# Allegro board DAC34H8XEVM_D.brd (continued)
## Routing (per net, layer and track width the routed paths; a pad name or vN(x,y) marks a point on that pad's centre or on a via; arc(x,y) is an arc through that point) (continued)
DA1N: length 67.2
  TOP w0.127: U1.F1 40.01,68.76 39.66,68.76 39.42,68.53 39.42,68.51 39.36,68.45 39.36,68.43 39.35,68.42
  TOP w0.152: 39.35,68.42 28.46,57.53 26.95,57.53 26.82,57.4 26.82,56.61 26.52,56.31 26.1,56.31 25.8,56.61 25.8,58.62 25.67,58.75 25.48,58.75 25.35,58.62 25.35,56.61 25.05,56.31 24.63,56.31 24.33,56.61 24.33,58.62 24.2,58.75 24.01,58.75 23.87,58.62 23.87,56.61 23.58,56.31 23.15,56.31 22.86,56.61 22.86,58.62 22.72,58.75 22.53,58.75 22.4,58.62 22.4,56.61 22.1,56.31 21.68,56.31 21.38,56.61 21.38,58.62 21.25,58.75 21.06,58.75 20.93,58.62 20.93,56.61 20.63,56.31 20.21,56.31 19.91,56.61 19.91,58.62 19.78,58.75 19.59,58.75 19.45,58.62 19.45,56.61 19.16,56.31 18.73,56.31 18.44,56.61 18.44,58.62 18.3,58.75 18.11,58.75 17.98,58.62 17.98,56.61 17.68,56.31 17.26,56.31 16.96,56.61 16.96,57.4 16.83,57.53 16.36,57.53 15.29,56.46 10.93,56.46 9.18,54.7 9.18,54.33 9.17,54.32 v2(9.17,54.02)
  BOTTOM w0.152: J13.159 7.71,54.02 7.74,54.05 8.5,54.05 8.52,54.03 9.15,54.03 v2(9.17,54.02)
DA1P: length 67.7
  TOP w0.127: 39.15,68.62 39.15,68.62 39.55,69.02 39.96,69.02 39.98,69.03 40.3,69.03 40.7,68.64 U1.F2
  TOP w0.152: v2(8.72,54.52) 8.9,54.69 8.9,54.82 10.82,56.74 15.17,56.74 16.24,57.81 16.95,57.81 17.24,57.51 17.24,56.73 17.38,56.59 17.57,56.59 17.7,56.73 17.7,58.73 18,59.03 18.42,59.03 18.72,58.73 18.72,56.73 18.85,56.59 19.04,56.59 19.17,56.73 19.17,58.73 19.47,59.03 19.89,59.03 20.19,58.73 20.19,56.73 20.32,56.59 20.51,56.59 20.65,56.73 20.65,58.73 20.94,59.03 21.37,59.03 21.66,58.73 21.66,56.73 21.8,56.59 21.99,56.59 22.12,56.73 22.12,58.73 22.42,59.03 22.84,59.03 23.14,58.73 23.14,56.73 23.27,56.59 23.46,56.59 23.59,56.73 23.59,58.73 23.89,59.03 24.31,59.03 24.61,58.73 24.61,56.73 24.74,56.59 24.93,56.59 25.07,56.73 25.07,58.73 25.36,59.03 25.78,59.03 26.08,58.73 26.08,56.73 26.22,56.59 26.41,56.59 26.54,56.73 26.54,57.51 26.84,57.81 28.35,57.81 39.15,68.62
  BOTTOM w0.152: v2(8.72,54.52) 8.64,54.43 7.79,54.43 7.71,54.52 J13.157
DA2N: length 66.8
  L3_PWR w0.127: U1.F3 41.74,68.39 41.35,68 41.35,67.69 41.09,67.43 38.75,67.43 33.05,61.72 31.61,61.72 31.34,61.45 31.34,60.71 31.21,60.58 31.03,60.58 30.91,60.71 30.91,62.59 30.63,62.87 30.24,62.87 29.97,62.59 29.97,60.71 29.84,60.58 29.66,60.58 29.54,60.71 29.54,62.59 29.26,62.87 28.87,62.87 28.6,62.59 28.6,60.71 28.47,60.58 28.29,60.58 28.16,60.71 28.16,62.59 27.89,62.87 27.5,62.87 27.22,62.59 27.22,60.71 27.1,60.58 26.92,60.58 26.79,60.71 26.79,62.59 26.52,62.87 26.13,62.87 25.85,62.59 25.85,60.71 25.73,60.58 25.55,60.58 25.42,60.71 25.42,62.59 25.15,62.87 24.76,62.87 24.48,62.59 24.48,60.71 24.35,60.58 24.18,60.58 24.05,60.71 24.05,62.59 23.77,62.87 23.38,62.87 23.11,62.59 23.11,60.71 22.98,60.58 22.8,60.58 22.68,60.71 22.68,61.45 22.4,61.72 21.05,61.72 16.06,56.73 15.12,56.73 14.81,56.42 9.52,56.42 9.49,56.45 9,56.45 8.72,56.18 8.72,55.79 8.79,55.72 v2(8.79,55.45)
  BOTTOM w0.152: J13.153 7.71,55.52 7.73,55.53 8.7,55.53 v2(8.79,55.45)
DA2P: length 67.6
  L3_PWR w0.127: v2(9.19,55.98) 9.38,56.17 14.91,56.17 15.22,56.48 16.17,56.48 21.16,61.47 22.3,61.47 22.42,61.34 22.42,60.6 22.7,60.33 23.09,60.33 23.36,60.6 23.36,62.48 23.49,62.61 23.67,62.61 23.8,62.48 23.8,60.6 24.07,60.33 24.46,60.33 24.74,60.6 24.74,62.48 24.86,62.61 25.04,62.61 25.17,62.48 25.17,60.6 25.44,60.33 25.83,60.33 26.11,60.6 26.11,62.48 26.23,62.61 26.41,62.61 26.54,62.48 26.54,60.6 26.81,60.33 27.2,60.33 27.48,60.6 27.48,62.48 27.6,62.61 27.78,62.61 27.91,62.48 27.91,60.6 28.19,60.33 28.57,60.33 28.85,60.6 28.85,62.48 28.98,62.61 29.16,62.61 29.28,62.48 29.28,60.6 29.56,60.33 29.95,60.33 30.22,60.6 30.22,62.48 30.35,62.61 30.53,62.61 30.65,62.48 30.65,60.6 30.93,60.33 31.32,60.33 31.59,60.6 31.59,61.34 31.72,61.47 33.15,61.47 38.86,67.18 39.5,67.18 39.62,67.05 39.62,66.95 39.95,66.63 41.1,66.63 41.35,66.87 41.35,67.2 41.58,67.43 41.9,67.43 42.15,67.67 42.15,68 42.54,68.39 U1.F4
  BOTTOM w0.152: J13.151 7.71,56.02 7.77,55.96 9.17,55.96 v2(9.19,55.98)
DA3N: length 67.3
  TOP w0.127: U1.E1 40.01,69.57 39.45,69.57
  TOP w0.152: 39.45,69.57 39.09,69.57 31.99,62.47 31.99,62.46 30.11,60.58 29.07,60.58 28.77,60.88 28.77,61.44 28.64,61.57 28.45,61.57 28.32,61.44 28.32,59.89 28.02,59.59 27.6,59.59 27.3,59.89 27.3,61.44 27.17,61.57 26.98,61.57 26.84,61.44 26.84,59.89 26.55,59.59 26.12,59.59 25.83,59.89 25.83,61.44 25.69,61.57 25.5,61.57 25.37,61.44 25.37,59.89 25.07,59.59 24.65,59.59 24.35,59.89 24.35,61.44 24.22,61.57 24.03,61.57 23.9,61.44 23.9,59.89 23.6,59.59 23.18,59.59 22.88,59.89 22.88,61.44 22.75,61.57 22.56,61.57 22.42,61.44 22.42,59.89 22.13,59.59 21.71,59.59 21.41,59.89 21.41,61.44 21.27,61.57 21.08,61.57 20.95,61.44 20.95,59.89 20.65,59.59 20.23,59.59 19.93,59.89 19.93,61.44 19.8,61.57 19.61,61.57 19.48,61.44 19.48,59.89 19.18,59.59 18.76,59.59 18.46,59.89 18.46,61.44 18.33,61.57 18.14,61.57 18,61.44 18,59.89 17.71,59.59 17.29,59.59 16.99,59.89 16.99,60.38 15.95,61.42 15.95,62.04 15.68,62.31 15.3,62.31 11.44,58.45 10.24,58.45 9.75,57.96 9.56,57.96 9.21,57.61 9.21,57.06 v2(9.25,57.02)
  BOTTOM w0.152: v2(9.25,57.02) 9.23,57.04 7.73,57.04 7.71,57.02 J13.147
DA3P: length 67.8
  TOP w0.127: U1.E2 40.7,69.44 40.29,69.84 39.61,69.84
  TOP w0.152: v2(8.75,57.52) 8.75,57.54 9.45,58.24 9.64,58.24 10.12,58.72 11.33,58.72 15.19,62.59 15.8,62.59 16.23,62.15 16.23,61.53 17.27,60.5 17.27,60 17.4,59.87 17.59,59.87 17.72,60 17.72,61.55 18.02,61.85 18.44,61.85 18.74,61.55 18.74,60 18.87,59.87 19.06,59.87 19.2,60 19.2,61.55 19.5,61.85 19.92,61.85 20.21,61.55 20.21,60 20.35,59.87 20.54,59.87 20.67,60 20.67,61.55 20.97,61.85 21.39,61.85 21.69,61.55 21.69,60 21.82,59.87 22.01,59.87 22.14,60 22.14,61.55 22.44,61.85 22.86,61.85 23.16,61.55 23.16,60 23.29,59.87 23.48,59.87 23.62,60 23.62,61.55 23.92,61.85 24.34,61.85 24.63,61.55 24.63,60 24.77,59.87 24.96,59.87 25.09,60 25.09,61.55 25.39,61.85 25.81,61.85 26.11,61.55 26.11,60 26.24,59.87 26.43,59.87 26.56,60 26.56,61.55 26.86,61.85 27.28,61.85 27.58,61.55 27.58,60 27.71,59.87 27.9,59.87 28.04,60 28.04,61.55 28.33,61.85 28.76,61.85 29.05,61.55 29.05,60.99 29.19,60.86 30,60.86 31.71,62.57 31.71,62.59 38.97,69.85 39.6,69.85 39.61,69.84
  BOTTOM w0.152: v2(8.75,57.52) 8.69,57.45 7.77,57.45 7.71,57.52 J13.145
DA4N: length 66.9
  L3_PWR w0.127: v2(8.79,58.52) 8.98,58.71 8.98,58.89 9.25,59.17 9.64,59.17 9.92,58.89 10.34,58.89 12.75,61.31 12.75,61.41 12.75,61.41 12.75,62.56 12.74,62.58 12.74,62.76 15,65.02 15.03,65.02 15.9,65.89 18.98,65.89 19.25,65.61 19.25,65.05 19.38,64.92 19.56,64.92 19.68,65.05 19.68,66.58 19.96,66.85 20.35,66.85 20.62,66.58 20.62,65.05 20.75,64.92 20.93,64.92 21.05,65.05 21.05,66.58 21.33,66.85 21.72,66.85 21.99,66.58 21.99,65.05 22.12,64.92 22.3,64.92 22.43,65.05 22.43,66.58 22.7,66.85 23.09,66.85 23.37,66.58 23.37,65.05 23.49,64.92 23.67,64.92 23.8,65.05 23.8,66.58 24.07,66.85 24.46,66.85 24.74,66.58 24.74,65.05 24.86,64.92 25.04,64.92 25.17,65.05 25.17,66.58 25.44,66.85 25.83,66.85 26.11,66.58 26.11,65.05 26.24,64.92 26.41,64.92 26.54,65.05 26.54,66.58 26.82,66.85 27.21,66.85 27.48,66.58 27.48,65.05 27.61,64.92 27.79,64.92 27.91,65.05 27.91,66.58 28.19,66.85 28.58,66.85 28.85,66.58 28.85,65.05 28.98,64.92 29.16,64.92 29.28,65.05 29.28,66.58 29.56,66.85 29.95,66.85 30.22,66.58 30.22,66.01 30.35,65.89 32.71,65.89 35.07,68.25 39.56,68.25 39.75,68.44 39.75,68.8 39.98,69.03 40.42,69.03 40.43,69.04 41.23,69.04 41.62,69.44 U1.E3
  BOTTOM w0.152: v2(8.79,58.52) 8.79,58.52 7.71,58.52 J13.141
DA4P: length 67.4
  L3_PWR w0.127: v2(9.45,58.7) 9.51,58.64 10.44,58.64 13.01,61.2 13.01,61.52 13,61.52 13,62.56 13.02,62.58 13.02,62.65 16,65.63 18.87,65.63 19,65.51 19,64.94 19.27,64.67 19.66,64.67 19.94,64.94 19.94,66.47 20.06,66.6 20.24,66.6 20.37,66.47 20.37,64.94 20.64,64.67 21.03,64.67 21.31,64.94 21.31,66.47 21.44,66.6 21.61,66.6 21.74,66.47 21.74,64.94 22.02,64.67 22.41,64.67 22.68,64.94 22.68,66.47 22.81,66.6 22.99,66.6 23.11,66.47 23.11,64.94 23.39,64.67 23.78,64.67 24.05,64.94 24.05,66.47 24.18,66.6 24.36,66.6 24.48,66.47 24.48,64.94 24.76,64.67 25.15,64.67 25.42,64.94 25.42,66.47 25.55,66.6 25.73,66.6 25.86,66.47 25.86,64.94 26.13,64.67 26.52,64.67 26.8,64.94 26.8,66.47 26.92,66.6 27.1,66.6 27.23,66.47 27.23,64.94 27.5,64.67 27.89,64.67 28.17,64.94 28.17,66.47 28.29,66.6 28.47,66.6 28.6,66.47 28.6,64.94 28.87,64.67 29.26,64.67 29.54,64.94 29.54,66.47 29.66,66.6 29.84,66.6 29.97,66.47 29.97,65.91 30.25,65.63 32.82,65.63 35.18,68 39.66,68 39.91,68.25 39.92,68.25 39.92,68.24 41.1,68.24 41.33,68.47 41.33,68.79 41.58,69.03 41.89,69.03 42.3,69.44 U1.E4
  BOTTOM w0.152: v2(9.45,58.7) 9.29,58.7 8.99,59 8.6,59 8.59,59.02 7.71,59.02 J13.139
DA5N: length 66.9
  TOP w0.152: U1.D1 40.02,70.35 38.58,70.35 32.28,64.06 32.27,64.06 31.48,63.27 30.62,63.27 30.17,63.72 30.17,64.23 30.04,64.36 29.85,64.36 29.72,64.23 29.72,62.78 29.42,62.48 29,62.48 28.7,62.78 28.7,64.23 28.57,64.36 28.38,64.36 28.24,64.23 28.24,62.78 27.95,62.48 27.53,62.48 27.23,62.78 27.23,64.23 27.09,64.36 26.91,64.36 26.77,64.23 26.77,62.78 26.47,62.48 26.05,62.48 25.76,62.78 25.76,64.23 25.62,64.36 25.43,64.36 25.3,64.23 25.3,62.78 25,62.48 24.58,62.48 24.28,62.78 24.28,64.23 24.15,64.36 23.96,64.36 23.82,64.23 23.82,62.78 23.53,62.48 23.11,62.48 22.81,62.78 22.81,64.23 22.68,64.36 22.49,64.36 22.35,64.23 22.35,62.78 22.05,62.48 21.63,62.48 21.34,62.78 21.34,64.23 21.2,64.36 21.01,64.36 20.88,64.23 20.88,62.78 20.58,62.48 20.16,62.48 19.86,62.78 19.86,64.23 19.73,64.36 19.54,64.36 19.41,64.23 19.41,62.78 19.11,62.48 18.69,62.48 18.39,62.78 18.39,64.23 18.26,64.36 18.07,64.36 17.93,64.23 17.93,62.78 17.63,62.48 17.21,62.48 16.92,62.78 16.92,63.29 16.78,63.42 16.27,63.42 15.63,64.06 14.58,64.06 11.2,60.68 10.22,60.68 10.12,60.78 9.44,60.78 9.3,60.64 v2(9.3,60.02)
  BOTTOM w0.152: J13.135 7.71,60.02 7.73,60.04 9.28,60.04 v2(9.3,60.02)
DA5P: length 67.4
  TOP w0.127: 39.54,70.63 40.3,70.63 40.7,70.24 U1.D2
  TOP w0.152: 39.54,70.63 38.46,70.63 32.17,64.34 32.16,64.34 31.37,63.55 30.74,63.55 30.45,63.84 30.45,64.35 30.16,64.64 29.74,64.64 29.44,64.35 29.44,62.9 29.3,62.76 29.12,62.76 28.98,62.9 28.98,64.35 28.68,64.64 28.26,64.64 27.97,64.35 27.97,62.9 27.83,62.76 27.64,62.76 27.51,62.9 27.51,64.35 27.21,64.64 26.79,64.64 26.49,64.35 26.49,62.9 26.36,62.76 26.17,62.76 26.03,62.9 26.03,64.35 25.74,64.64 25.32,64.64 25.02,64.35 25.02,62.9 24.88,62.76 24.7,62.76 24.56,62.9 24.56,64.35 24.26,64.64 23.84,64.64 23.55,64.35 23.55,62.9 23.41,62.76 23.22,62.76 23.09,62.9 23.09,64.35 22.79,64.64 22.37,64.64 22.07,64.35 22.07,62.9 21.94,62.76 21.75,62.76 21.62,62.9 21.62,64.35 21.32,64.64 20.9,64.64 20.6,64.35 20.6,62.9 20.47,62.76 20.28,62.76 20.14,62.9 20.14,64.35 19.84,64.64 19.42,64.64 19.13,64.35 19.13,62.9 18.99,62.76 18.8,62.76 18.67,62.9 18.67,64.35 18.37,64.64 17.95,64.64 17.65,64.35 17.65,62.9 17.52,62.76 17.33,62.76 17.2,62.9 17.2,63.41 16.9,63.7 16.38,63.7 15.75,64.34 14.46,64.34 11.09,60.96 10.34,60.96 10.24,61.06 9.32,61.06 8.81,60.55 v2(8.81,60.52)
  BOTTOM w0.152: v2(8.81,60.52) 8.74,60.45 7.78,60.45 7.71,60.52 J13.133
DA6N: length 67.5
  L3_PWR w0.127: U1.D3 41.66,70.24 41.52,70.38 41.4,70.38 41.33,70.31 41.33,70.07 41.1,69.84 39.98,69.84 39.75,70.07 39.75,70.44 39.67,70.51 35.64,70.51 34.4,69.27 30.77,69.27 30.36,68.86 30.36,68.3 30.09,68.02 29.7,68.02 29.42,68.3 29.42,69.83 29.3,69.95 29.12,69.95 28.99,69.83 28.99,68.3 28.72,68.02 28.33,68.02 28.05,68.3 28.05,69.83 27.93,69.95 27.75,69.95 27.62,69.83 27.62,68.3 27.35,68.02 26.96,68.02 26.68,68.3 26.68,69.83 26.55,69.95 26.38,69.95 26.25,69.83 26.25,68.3 25.97,68.02 25.58,68.02 25.31,68.3 25.31,69.83 25.18,69.95 25,69.95 24.88,69.83 24.88,68.3 24.6,68.02 24.21,68.02 23.94,68.3 23.94,69.83 23.81,69.95 23.63,69.95 23.51,69.83 23.51,68.3 23.23,68.02 22.84,68.02 22.57,68.3 22.57,69.83 22.44,69.95 22.26,69.95 22.13,69.83 22.13,68.3 21.86,68.02 21.47,68.02 21.19,68.3 21.19,69.83 21.07,69.95 20.89,69.95 20.76,69.83 20.76,68.3 20.49,68.02 20.1,68.02 19.82,68.3 19.82,69.83 19.7,69.95 19.52,69.95 19.39,69.83 19.39,68.3 19.12,68.02 18.73,68.02 18.45,68.3 18.45,68.86 18.32,68.99 16.43,68.99 9.22,61.77 v2(9.22,61.52)
  BOTTOM w0.152: J13.129 7.71,61.52 7.78,61.59 8.48,61.59 8.53,61.54 9.2,61.54 v2(9.22,61.52)
DA6P: length 67.3
  L3_PWR w0.127: v2(8.73,62.02) 9.11,62.02 16.33,69.24 18.43,69.24 18.71,68.97 18.71,68.4 18.83,68.28 19.01,68.28 19.14,68.4 19.14,69.93 19.41,70.21 19.8,70.21 20.08,69.93 20.08,68.4 20.2,68.28 20.38,68.28 20.51,68.4 20.51,69.93 20.78,70.21 21.17,70.21 21.45,69.93 21.45,68.4 21.58,68.28 21.75,68.28 21.88,68.4 21.88,69.93 22.16,70.21 22.55,70.21 22.82,69.93 22.82,68.4 22.95,68.28 23.13,68.28 23.25,68.4 23.25,69.93 23.53,70.21 23.92,70.21 24.19,69.93 24.19,68.4 24.32,68.28 24.5,68.28 24.62,68.4 24.62,69.93 24.9,70.21 25.29,70.21 25.56,69.93 25.56,68.4 25.69,68.28 25.87,68.28 26,68.4 26,69.93 26.27,70.21 26.66,70.21 26.93,69.93 26.93,68.4 27.06,68.28 27.24,68.28 27.37,68.4 27.37,69.93 27.64,70.21 28.03,70.21 28.31,69.93 28.31,68.4 28.43,68.28 28.61,68.28 28.74,68.4 28.74,69.93 29.01,70.21 29.4,70.21 29.68,69.93 29.68,68.4 29.8,68.28 29.98,68.28 30.11,68.4 30.11,68.97 30.66,69.52 34.29,69.52 35.53,70.76 39.78,70.76 39.91,70.63 41.9,70.63 42.3,70.24 U1.D4
  BOTTOM w0.152: J13.127 7.71,62.02 7.78,61.95 8.66,61.95 v2(8.73,62.02)
DA7N: length 67
  TOP w0.127: U1.C1 40.01,71.16 38.73,71.16
  TOP w0.152: v2(9.22,63.02) 9.22,63.6 9.43,63.81 12.85,63.81 15.36,66.32 18.47,66.32 18.6,66.19 18.6,65.52 18.9,65.23 19.32,65.23 19.62,65.52 19.62,67.28 19.75,67.41 19.94,67.41 20.07,67.28 20.07,65.52 20.37,65.23 20.79,65.23 21.09,65.52 21.09,67.28 21.22,67.41 21.41,67.41 21.55,67.28 21.55,65.52 21.84,65.23 22.26,65.23 22.56,65.52 22.56,67.28 22.7,67.41 22.89,67.41 23.02,67.28 23.02,65.52 23.32,65.23 23.74,65.23 24.04,65.52 24.04,67.28 24.17,67.41 24.36,67.41 24.49,67.28 24.49,65.52 24.79,65.23 25.21,65.23 25.51,65.52 25.51,67.28 25.64,67.41 25.83,67.41 25.97,67.28 25.97,65.52 26.26,65.23 26.68,65.23 26.98,65.52 26.98,67.28 27.12,67.41 27.31,67.41 27.44,67.28 27.44,65.52 27.74,65.23 28.16,65.23 28.45,65.52 28.45,67.28 28.59,67.41 28.78,67.41 28.91,67.28 28.91,65.52 29.21,65.23 29.63,65.23 29.93,65.52 29.93,67.28 30.06,67.41 30.25,67.41 30.39,67.28 30.39,66.62 30.68,66.32 33.42,66.32 38.27,71.17 38.6,71.17 38.61,71.16 38.73,71.16
  BOTTOM w0.152: J13.123 7.71,63.02 7.81,63.12 8.48,63.12 8.56,63.04 9.2,63.04 v2(9.22,63.02)
DA7P: length 67.5
  TOP w0.127: 38.73,71.45 38.74,71.44 39.96,71.44 39.97,71.44 40.31,71.44 40.31,71.44 40.37,71.44 40.77,71.04 U1.C2
  TOP w0.152: v2(8.76,63.52) 8.76,63.54 9.31,64.09 12.73,64.09 15.24,66.6 18.58,66.6 18.88,66.3 18.88,65.64 19.01,65.51 19.2,65.51 19.34,65.64 19.34,67.39 19.63,67.69 20.05,67.69 20.35,67.39 20.35,65.64 20.49,65.51 20.68,65.51 20.81,65.64 20.81,67.39 21.11,67.69 21.53,67.69 21.83,67.39 21.83,65.64 21.96,65.51 22.15,65.51 22.28,65.64 22.28,67.39 22.58,67.69 23,67.69 23.3,67.39 23.3,65.64 23.43,65.51 23.62,65.51 23.76,65.64 23.76,67.39 24.05,67.69 24.47,67.69 24.77,67.39 24.77,65.64 24.91,65.51 25.1,65.51 25.23,65.64 25.23,67.39 25.53,67.69 25.95,67.69 26.25,67.39 26.25,65.64 26.38,65.51 26.57,65.51 26.7,65.64 26.7,67.39 27,67.69 27.42,67.69 27.72,67.39 27.72,65.64 27.85,65.51 28.04,65.51 28.18,65.64 28.18,67.39 28.47,67.69 28.89,67.69 29.19,67.39 29.19,65.64 29.33,65.51 29.51,65.51 29.65,65.64 29.65,67.39 29.95,67.69 30.37,67.69 30.66,67.39 30.66,66.73 30.8,66.6 33.3,66.6 38.15,71.45 38.73,71.45
  BOTTOM w0.152: J13.121 7.71,63.52 7.81,63.42 8.66,63.42 v2(8.76,63.52)
DA8N: length 66.8
  L3_PWR w0.127: U1.C3 41.62,71.04 41.23,71.43 39.91,71.43 39.67,71.68 39.67,71.85 39.54,71.98 38.23,71.98 38.11,71.85 38.11,71.58 37.83,71.31 37.44,71.31 37.17,71.58 37.17,72.52 37.04,72.64 36.86,72.64 36.73,72.52 36.73,71.58 36.46,71.31 36.07,71.31 35.79,71.58 35.79,72.52 35.67,72.64 35.49,72.64 35.36,72.52 35.36,71.58 35.09,71.31 34.7,71.31 34.42,71.58 34.42,72.52 34.3,72.64 34.12,72.64 33.99,72.52 33.99,71.58 33.72,71.31 33.33,71.31 33.05,71.58 33.05,72.52 32.93,72.64 32.75,72.64 32.62,72.52 32.62,71.58 32.34,71.31 31.96,71.31 31.68,71.58 31.68,72.52 31.55,72.64 31.37,72.64 31.25,72.52 31.25,71.58 30.97,71.31 30.58,71.31 30.31,71.58 30.31,72.52 30.18,72.64 30,72.64 29.88,72.52 29.88,71.58 29.6,71.31 29.21,71.31 28.94,71.58 28.94,72.52 28.81,72.64 28.63,72.64 28.51,72.52 28.51,71.58 28.23,71.31 27.84,71.31 27.57,71.58 27.57,72.52 27.44,72.64 27.26,72.64 27.13,72.52 27.13,71.58 26.86,71.31 26.47,71.31 26.19,71.58 26.19,72.52 26.07,72.64 25.89,72.64 25.76,72.52 25.76,71.58 25.49,71.31 25.1,71.31 24.82,71.58 24.82,72.52 24.7,72.64 24.52,72.64 24.39,72.52 24.39,71.58 24.12,71.31 23.73,71.31 23.45,71.58 23.45,72.52 23.32,72.64 23.15,72.64 23.02,72.52 23.02,71.58 22.74,71.31 22.35,71.31 22.08,71.58 22.08,72.52 21.95,72.64 21.77,72.64 21.65,72.52 21.65,71.58 21.37,71.31 20.98,71.31 20.71,71.58 20.71,72.52 20.58,72.64 20.4,72.64 20.28,72.52 20.28,71.58 20,71.31 19.61,71.31 19.34,71.58 19.34,72.52 19.21,72.64 19.03,72.64 18.9,72.52 18.9,72.25 18.63,71.98 17.52,71.98 15.21,69.67 12.9,69.67 11.92,70.65 11.92,70.65 11.52,71.06 10.47,71.06 10.3,71.22 9.76,71.22 9.54,71.01 8.85,71.01 v2(8.84,71.02)
  BOTTOM w0.152: v2(8.84,71.02) 8.74,71.12 7.79,71.12 7.71,71.04 J13.111
DA8P: length 67.7
  L3_PWR w0.127: v2(9.35,71.48) 10.41,71.48 10.57,71.31 11.62,71.31 12.18,70.76 12.18,70.76 13,69.93 15.11,69.93 17.41,72.23 18.52,72.23 18.65,72.36 18.65,72.62 18.93,72.9 19.31,72.9 19.59,72.62 19.59,71.69 19.72,71.56 19.9,71.56 20.02,71.69 20.02,72.62 20.3,72.9 20.69,72.9 20.96,72.62 20.96,71.69 21.09,71.56 21.27,71.56 21.39,71.69 21.39,72.62 21.67,72.9 22.06,72.9 22.33,72.62 22.33,71.69 22.46,71.56 22.64,71.56 22.76,71.69 22.76,72.62 23.04,72.9 23.43,72.9 23.7,72.62 23.7,71.69 23.83,71.56 24.01,71.56 24.14,71.69 24.14,72.62 24.41,72.9 24.8,72.9 25.08,72.62 25.08,71.69 25.2,71.56 25.38,71.56 25.51,71.69 25.51,72.62 25.78,72.9 26.17,72.9 26.45,72.62 26.45,71.69 26.57,71.56 26.75,71.56 26.88,71.69 26.88,72.62 27.15,72.9 27.54,72.9 27.82,72.62 27.82,71.69 27.95,71.56 28.12,71.56 28.25,71.69 28.25,72.62 28.53,72.9 28.92,72.9 29.19,72.62 29.19,71.69 29.32,71.56 29.5,71.56 29.62,71.69 29.62,72.62 29.9,72.9 30.29,72.9 30.56,72.62 30.56,71.69 30.69,71.56 30.87,71.56 30.99,71.69 30.99,72.62 31.27,72.9 31.66,72.9 31.93,72.62 31.93,71.69 32.06,71.56 32.24,71.56 32.37,71.69 32.37,72.62 32.64,72.9 33.03,72.9 33.31,72.62 33.31,71.69 33.43,71.56 33.61,71.56 33.74,71.69 33.74,72.62 34.01,72.9 34.4,72.9 34.68,72.62 34.68,71.69 34.8,71.56 34.98,71.56 35.11,71.69 35.11,72.62 35.38,72.9 35.77,72.9 36.05,72.62 36.05,71.69 36.18,71.56 36.35,71.56 36.48,71.69 36.48,72.62 36.76,72.9 37.15,72.9 37.42,72.62 37.42,71.69 37.55,71.56 37.73,71.56 37.85,71.69 37.85,71.96 38.13,72.23 41.1,72.23 41.33,72 41.33,71.69 41.58,71.44 41.89,71.44 42.3,71.04 U1.C4
  BOTTOM w0.152: v2(9.35,71.48) 9.06,71.48 9.04,71.5 7.74,71.5 7.71,71.54 J13.109
DA9N: length 67.5
  TOP w0.127: 39.44,72.1 39.56,72.1 39.57,72.11 39.87,72.11 U1.B1
  TOP w0.152: 39.44,72.1 37.82,72.1 37.5,71.78 36.39,71.78 36.09,72.08 36.09,72.43 35.96,72.57 35.77,72.57 35.63,72.43 35.63,71.29 35.33,70.99 34.91,70.99 34.62,71.29 34.62,72.43 34.48,72.57 34.29,72.57 34.16,72.43 34.16,71.29 33.86,70.99 33.44,70.99 33.14,71.29 33.14,72.43 33.01,72.57 32.82,72.57 32.69,72.43 32.69,71.29 32.39,70.99 31.97,70.99 31.67,71.29 31.67,72.43 31.54,72.57 31.35,72.57 31.21,72.43 31.21,71.29 30.91,70.99 30.49,70.99 30.2,71.29 30.2,72.43 30.06,72.57 29.87,72.57 29.74,72.43 29.74,71.29 29.44,70.99 29.02,70.99 28.72,71.29 28.72,72.43 28.59,72.57 28.4,72.57 28.27,72.43 28.27,71.29 27.97,70.99 27.55,70.99 27.25,71.29 27.25,72.43 27.12,72.57 26.93,72.57 26.79,72.43 26.79,71.29 26.5,70.99 26.07,70.99 25.78,71.29 25.78,72.43 25.64,72.57 25.45,72.57 25.32,72.43 25.32,71.29 25.02,70.99 24.6,70.99 24.3,71.29 24.3,72.43 24.17,72.57 23.98,72.57 23.85,72.43 23.85,71.29 23.55,70.99 23.13,70.99 22.83,71.29 22.83,72.43 22.7,72.57 22.51,72.57 22.37,72.43 22.37,71.29 22.08,70.99 21.65,70.99 21.36,71.29 21.36,72.43 21.22,72.57 21.03,72.57 20.9,72.43 20.9,71.29 20.6,70.99 20.18,70.99 19.88,71.29 19.88,72.43 19.75,72.57 19.56,72.57 19.43,72.43 19.43,71.29 19.13,70.99 18.71,70.99 18.41,71.29 18.41,72.43 18.28,72.57 18.09,72.57 17.95,72.43 17.95,72.09 16.02,70.15 15.09,70.15 12.52,72.72 9.45,72.72 v2(9.27,72.54)
  BOTTOM w0.152: v2(9.27,72.54) 9.25,72.56 8.63,72.56 8.56,72.62 7.79,72.62 ; 7.71,72.54 7.79,72.62 ; 7.79,72.62 7.79,72.53 J13.105
DA9P: length 67.4
  TOP w0.127: 39.44,72.38 39.88,72.38 U1.A1
  TOP w0.152: 39.44,72.38 37.71,72.38 37.39,72.06 36.5,72.06 36.37,72.19 36.37,72.55 36.07,72.85 35.65,72.85 35.35,72.55 35.35,71.41 35.22,71.27 35.03,71.27 34.9,71.41 34.9,72.55 34.6,72.85 34.18,72.85 33.88,72.55 33.88,71.41 33.75,71.27 33.56,71.27 33.42,71.41 33.42,72.55 33.12,72.85 32.7,72.85 32.41,72.55 32.41,71.41 32.27,71.27 32.08,71.27 31.95,71.41 31.95,72.55 31.65,72.85 31.23,72.85 30.93,72.55 30.93,71.41 30.8,71.27 30.61,71.27 30.48,71.41 30.48,72.55 30.18,72.85 29.76,72.85 29.46,72.55 29.46,71.41 29.33,71.27 29.14,71.27 29,71.41 29,72.55 28.71,72.85 28.28,72.85 27.99,72.55 27.99,71.41 27.85,71.27 27.66,71.27 27.53,71.41 27.53,72.55 27.23,72.85 26.81,72.85 26.51,72.55 26.51,71.41 26.38,71.27 26.19,71.27 26.06,71.41 26.06,72.55 25.76,72.85 25.34,72.85 25.04,72.55 25.04,71.41 24.91,71.27 24.72,71.27 24.58,71.41 24.58,72.55 24.29,72.85 23.86,72.85 23.57,72.55 23.57,71.41 23.43,71.27 23.24,71.27 23.11,71.41 23.11,72.55 22.81,72.85 22.39,72.85 22.09,72.55 22.09,71.41 21.96,71.27 21.77,71.27 21.64,71.41 21.64,72.55 21.34,72.85 20.92,72.85 20.62,72.55 20.62,71.41 20.49,71.27 20.3,71.27 20.16,71.41 20.16,72.55 19.87,72.85 19.44,72.85 19.15,72.55 19.15,71.41 19.01,71.27 18.82,71.27 18.69,71.41 18.69,72.55 18.39,72.85 17.97,72.85 17.67,72.55 17.67,72.21 15.9,70.43 15.2,70.43 12.64,73 11.04,73 11,73.04 v2(8.83,73.04)
  BOTTOM w0.152: 7.71,73.04 7.77,72.97 ; 7.77,72.97 7.77,73.04 J13.103 ; 7.77,72.97 8.76,72.97 v2(8.83,73.04)
DA10N: length 67.8
  TOP w0.127: U1.B2 40.91,71.84 40.53,72.22 40.53,73.03
  TOP w0.152: v2(9.25,74.04) 13.26,74.04 14,73.3 15.29,73.3 16.03,74.04 16.51,74.04 16.81,74.34 16.81,74.62 16.94,74.75 17.13,74.75 17.26,74.62 17.26,73.63 17.56,73.33 17.98,73.33 18.28,73.63 18.28,74.62 18.41,74.75 18.6,74.75 18.74,74.62 18.74,73.63 19.03,73.33 19.45,73.33 19.75,73.63 19.75,74.62 19.89,74.75 20.08,74.75 20.21,74.62 20.21,73.63 20.51,73.33 20.93,73.33 21.23,73.63 21.23,74.62 21.36,74.75 21.55,74.75 21.68,74.62 21.68,73.63 21.98,73.33 22.4,73.33 22.7,73.63 22.7,74.62 22.83,74.75 23.02,74.75 23.16,74.62 23.16,73.63 23.45,73.33 23.87,73.33 24.17,73.63 24.17,74.62 24.31,74.75 24.5,74.75 24.63,74.62 24.63,73.63 24.93,73.33 25.35,73.33 25.65,73.63 25.65,74.62 25.78,74.75 25.97,74.75 26.1,74.62 26.1,73.63 26.4,73.33 26.82,73.33 27.12,73.63 27.12,74.62 27.25,74.75 27.44,74.75 27.58,74.62 27.58,73.63 27.87,73.33 28.29,73.33 28.59,73.63 28.59,74.62 28.73,74.75 28.91,74.75 29.05,74.62 29.05,73.63 29.35,73.33 29.77,73.33 30.06,73.63 30.06,74.62 30.2,74.75 30.39,74.75 30.52,74.62 30.52,73.63 30.82,73.33 31.24,73.33 31.54,73.63 31.54,74.62 31.67,74.75 31.86,74.75 32,74.62 32,73.63 32.29,73.33 32.71,73.33 33.01,73.63 33.01,74.62 33.14,74.75 33.33,74.75 33.47,74.62 33.47,73.63 33.77,73.33 34.19,73.33 34.48,73.63 34.48,74.62 34.62,74.75 34.81,74.75 34.94,74.62 34.94,73.63 35.24,73.33 35.66,73.33 35.96,73.63 35.96,74.62 36.09,74.75 36.28,74.75 36.41,74.62 36.41,73.63 36.71,73.33 37.13,73.33 37.43,73.63 37.43,73.91 37.56,74.04 38.61,74.04 39.35,73.3 40.26,73.3 40.53,73.03
  BOTTOM w0.152: J13.99 7.71,74.04 7.79,74.12 8.54,74.12 8.6,74.06 9.23,74.06 v2(9.25,74.04)
DA10P: length 67.4
  TOP w0.127: 40.82,73.14 40.82,72.76 U1.A2
  TOP w0.152: 40.82,73.14 40.38,73.58 39.46,73.58 38.72,74.32 37.45,74.32 37.15,74.02 37.15,73.74 37.02,73.61 36.83,73.61 36.69,73.74 36.69,74.73 36.4,75.03 35.98,75.03 35.68,74.73 35.68,73.74 35.54,73.61 35.35,73.61 35.22,73.74 35.22,74.73 34.92,75.03 34.5,75.03 34.2,74.73 34.2,73.74 34.07,73.61 33.88,73.61 33.75,73.74 33.75,74.73 33.45,75.03 33.03,75.03 32.73,74.73 32.73,73.74 32.6,73.61 32.41,73.61 32.27,73.74 32.27,74.73 31.98,75.03 31.56,75.03 31.26,74.73 31.26,73.74 31.12,73.61 30.94,73.61 30.8,73.74 30.8,74.73 30.5,75.03 30.08,75.03 29.79,74.73 29.79,73.74 29.65,73.61 29.46,73.61 29.33,73.74 29.33,74.73 29.03,75.03 28.61,75.03 28.31,74.73 28.31,73.74 28.18,73.61 27.99,73.61 27.85,73.74 27.85,74.73 27.56,75.03 27.14,75.03 26.84,74.73 26.84,73.74 26.71,73.61 26.52,73.61 26.38,73.74 26.38,74.73 26.08,75.03 25.66,75.03 25.37,74.73 25.37,73.74 25.23,73.61 25.04,73.61 24.91,73.74 24.91,74.73 24.61,75.03 24.19,75.03 23.89,74.73 23.89,73.74 23.76,73.61 23.57,73.61 23.44,73.74 23.44,74.73 23.14,75.03 22.72,75.03 22.42,74.73 22.42,73.74 22.29,73.61 22.1,73.61 21.96,73.74 21.96,74.73 21.66,75.03 21.24,75.03 20.95,74.73 20.95,73.74 20.81,73.61 20.62,73.61 20.49,73.74 20.49,74.73 20.19,75.03 19.77,75.03 19.47,74.73 19.47,73.74 19.34,73.61 19.15,73.61 19.02,73.74 19.02,74.73 18.72,75.03 18.3,75.03 18,74.73 18,73.74 17.87,73.61 17.68,73.61 17.54,73.74 17.54,74.73 17.25,75.03 16.82,75.03 16.53,74.73 16.53,74.45 16.39,74.32 15.91,74.32 15.17,73.58 14.11,73.58 13.37,74.32 9.61,74.32 9.44,74.5 8.84,74.5 v2(8.8,74.54)
  BOTTOM w0.152: J13.97 7.71,74.54 7.77,74.47 8.73,74.47 v2(8.8,74.54)
DA11N: length 67.4
  TOP w0.127: 41.33,73.28 41.34,73.28 41.34,73.27 41.33,73.26 41.33,72.23 41.73,71.84 U1.B3
  TOP w0.152: v2(9.25,75.54) 9.63,75.92 13.23,75.92 14.1,75.06 15.44,75.06 16.74,76.35 17.48,76.35 17.61,76.22 17.61,75.94 17.91,75.64 18.33,75.64 18.63,75.94 18.63,76.93 18.76,77.06 18.95,77.06 19.09,76.93 19.09,75.94 19.38,75.64 19.8,75.64 20.1,75.94 20.1,76.93 20.24,77.06 20.42,77.06 20.56,76.93 20.56,75.94 20.86,75.64 21.28,75.64 21.57,75.94 21.57,76.93 21.71,77.06 21.9,77.06 22.03,76.93 22.03,75.94 22.33,75.64 22.75,75.64 23.05,75.94 23.05,76.93 23.18,77.06 23.37,77.06 23.5,76.93 23.5,75.94 23.8,75.64 24.22,75.64 24.52,75.94 24.52,76.93 24.65,77.06 24.84,77.06 24.98,76.93 24.98,75.94 25.28,75.64 25.7,75.64 25.99,75.94 25.99,76.93 26.13,77.06 26.32,77.06 26.45,76.93 26.45,75.94 26.75,75.64 27.17,75.64 27.47,75.94 27.47,76.93 27.6,77.06 27.79,77.06 27.92,76.93 27.92,75.94 28.22,75.64 28.64,75.64 28.94,75.94 28.94,76.93 29.07,77.06 29.26,77.06 29.4,76.93 29.4,75.94 29.7,75.64 30.12,75.64 30.41,75.94 30.41,76.93 30.55,77.06 30.74,77.06 30.87,76.93 30.87,75.94 31.17,75.64 31.59,75.64 31.89,75.94 31.89,76.93 32.02,77.06 32.21,77.06 32.34,76.93 32.34,75.94 32.64,75.64 33.06,75.64 33.36,75.94 33.36,76.93 33.49,77.06 33.68,77.06 33.82,76.93 33.82,75.94 34.11,75.64 34.54,75.64 34.83,75.94 34.83,76.93 34.97,77.06 35.16,77.06 35.29,76.93 35.29,75.94 35.59,75.64 36.01,75.64 36.31,75.94 36.31,76.56 36.74,76.99 37.34,76.99 39.8,74.52 40.09,74.52 41.33,73.28
  BOTTOM w0.152: v2(9.25,75.54) 9.23,75.56 8.58,75.56 8.52,75.62 7.79,75.62 7.71,75.54 J13.93
DA11P: length 66.9
  TOP w0.127: U1.A3 41.59,72.79 41.59,73.16 41.6,73.17 41.6,73.41 41.55,73.46 41.53,73.48
  TOP w0.152: v2(8.78,76.04) 8.82,76 9.31,76 9.51,76.2 13.35,76.2 14.21,75.34 15.33,75.34 16.62,76.63 17.59,76.63 17.89,76.33 17.89,76.05 18.03,75.92 18.21,75.92 18.35,76.05 18.35,77.05 18.65,77.34 19.07,77.34 19.36,77.05 19.36,76.05 19.5,75.92 19.69,75.92 19.82,76.05 19.82,77.05 20.12,77.34 20.54,77.34 20.84,77.05 20.84,76.05 20.97,75.92 21.16,75.92 21.3,76.05 21.3,77.05 21.59,77.34 22.01,77.34 22.31,77.05 22.31,76.05 22.44,75.92 22.63,75.92 22.77,76.05 22.77,77.05 23.07,77.34 23.49,77.34 23.78,77.05 23.78,76.05 23.92,75.92 24.11,75.92 24.24,76.05 24.24,77.05 24.54,77.34 24.96,77.34 25.26,77.05 25.26,76.05 25.39,75.92 25.58,75.92 25.71,76.05 25.71,77.05 26.01,77.34 26.43,77.34 26.73,77.05 26.73,76.05 26.86,75.92 27.05,75.92 27.19,76.05 27.19,77.05 27.49,77.34 27.91,77.34 28.2,77.05 28.2,76.05 28.34,75.92 28.53,75.92 28.66,76.05 28.66,77.05 28.96,77.34 29.38,77.34 29.68,77.05 29.68,76.05 29.81,75.92 30,75.92 30.13,76.05 30.13,77.05 30.43,77.34 30.85,77.34 31.15,77.05 31.15,76.05 31.28,75.92 31.47,75.92 31.61,76.05 31.61,77.05 31.9,77.34 32.33,77.34 32.62,77.05 32.62,76.05 32.76,75.92 32.95,75.92 33.08,76.05 33.08,77.05 33.38,77.34 33.8,77.34 34.1,77.05 34.1,76.05 34.23,75.92 34.42,75.92 34.55,76.05 34.55,77.05 34.85,77.34 35.27,77.34 35.57,77.05 35.57,76.05 35.7,75.92 35.89,75.92 36.03,76.05 36.03,76.67 36.62,77.27 37.45,77.27 39.92,74.8 40.21,74.8 41.53,73.48
  BOTTOM w0.152: J13.91 7.71,76.04 7.8,75.95 8.69,75.95 v2(8.78,76.04)
DA12N: length 67.8
  TOP w0.127: 42.13,73.06 42.13,72.17 42.46,71.84 U1.B4
  TOP w0.152: 42.13,73.06 42.13,73.08 42.14,73.08 42.14,73.62 37.04,78.71 35.16,78.71 34.87,79.01 34.87,79.32 34.73,79.45 34.54,79.45 34.41,79.32 34.41,78.28 34.11,77.98 33.69,77.98 33.39,78.28 33.39,79.32 33.26,79.45 33.07,79.45 32.94,79.32 32.94,78.28 32.64,77.98 32.22,77.98 31.92,78.28 31.92,79.32 31.79,79.45 31.6,79.45 31.46,79.32 31.46,78.28 31.16,77.98 30.74,77.98 30.45,78.28 30.45,79.32 30.31,79.45 30.12,79.45 29.99,79.32 29.99,78.28 29.69,77.98 29.27,77.98 28.97,78.28 28.97,79.32 28.84,79.45 28.65,79.45 28.52,79.32 28.52,78.28 28.22,77.98 27.8,77.98 27.5,78.28 27.5,79.32 27.37,79.45 27.18,79.45 27.04,79.32 27.04,78.28 26.74,77.98 26.32,77.98 26.03,78.28 26.03,79.32 25.89,79.45 25.7,79.45 25.57,79.32 25.57,78.28 25.27,77.98 24.85,77.98 24.55,78.28 24.55,79.32 24.42,79.45 24.23,79.45 24.1,79.32 24.1,78.28 23.8,77.98 23.38,77.98 23.08,78.28 23.08,79.32 22.95,79.45 22.76,79.45 22.62,79.32 22.62,78.28 22.33,77.98 21.9,77.98 21.61,78.28 21.61,79.32 21.47,79.45 21.28,79.45 21.15,79.32 21.15,78.28 20.85,77.98 20.43,77.98 20.13,78.28 20.13,79.32 20,79.45 19.81,79.45 19.68,79.32 19.68,78.28 19.38,77.98 18.96,77.98 18.66,78.28 18.66,79.32 18.53,79.45 18.34,79.45 18.2,79.32 18.2,78.28 17.91,77.98 17.48,77.98 17.18,78.28 15.93,78.28 15.6,77.96 10.19,77.96 9.4,77.17 9.37,77.17 v2(9.25,77.04)
  BOTTOM w0.152: J13.87 7.71,77.04 7.78,77.11 8.53,77.11 8.58,77.06 9.23,77.06 v2(9.25,77.04)
DA12P: length 67.2
  TOP w0.127: U1.A4 42.42,72.76 42.42,73.08
  TOP w0.152: v2(8.78,77.54) 8.83,77.5 9.34,77.5 10.07,78.24 15.48,78.24 15.81,78.56 17.3,78.56 17.6,78.26 17.79,78.26 17.92,78.39 17.92,79.43 18.22,79.73 18.64,79.73 18.94,79.43 18.94,78.39 19.07,78.26 19.26,78.26 19.4,78.39 19.4,79.43 19.69,79.73 20.12,79.73 20.41,79.43 20.41,78.39 20.55,78.26 20.74,78.26 20.87,78.39 20.87,79.43 21.17,79.73 21.59,79.73 21.89,79.43 21.89,78.39 22.02,78.26 22.21,78.26 22.34,78.39 22.34,79.43 22.64,79.73 23.06,79.73 23.36,79.43 23.36,78.39 23.49,78.26 23.68,78.26 23.82,78.39 23.82,79.43 24.11,79.73 24.54,79.73 24.83,79.43 24.83,78.39 24.97,78.26 25.16,78.26 25.29,78.39 25.29,79.43 25.59,79.73 26.01,79.73 26.31,79.43 26.31,78.39 26.44,78.26 26.63,78.26 26.76,78.39 26.76,79.43 27.06,79.73 27.48,79.73 27.78,79.43 27.78,78.39 27.91,78.26 28.1,78.26 28.24,78.39 28.24,79.43 28.53,79.73 28.95,79.73 29.25,79.43 29.25,78.39 29.39,78.26 29.58,78.26 29.71,78.39 29.71,79.43 30.01,79.73 30.43,79.73 30.73,79.43 30.73,78.39 30.86,78.26 31.05,78.26 31.18,78.39 31.18,79.43 31.48,79.73 31.9,79.73 32.2,79.43 32.2,78.39 32.33,78.26 32.52,78.26 32.66,78.39 32.66,79.43 32.95,79.73 33.37,79.73 33.67,79.43 33.67,78.39 33.81,78.26 34,78.26 34.13,78.39 34.13,79.43 34.43,79.73 34.85,79.73 35.14,79.43 35.14,79.13 35.28,78.99 37.16,78.99 42.42,73.74 42.42,73.08
  BOTTOM w0.152: J13.85 7.71,77.54 7.78,77.47 8.71,77.47 v2(8.78,77.54)
DA13N: length 67.7
  TOP w0.127: 42.95,73.07 42.95,72.22 43.33,71.84 U1.B5
  TOP w0.152: 42.95,73.07 42.95,74.91 36.2,81.66 33.46,81.66 33.16,81.96 33.16,82.26 33.02,82.4 32.83,82.4 32.7,82.26 32.7,81.22 32.4,80.92 31.98,80.92 31.68,81.22 31.68,82.26 31.55,82.4 31.36,82.4 31.23,82.26 31.23,81.22 30.93,80.92 30.51,80.92 30.21,81.22 30.21,82.26 30.08,82.4 29.89,82.4 29.75,82.26 29.75,81.22 29.46,80.92 29.04,80.92 28.74,81.22 28.74,82.26 28.6,82.4 28.42,82.4 28.28,82.26 28.28,81.22 27.98,80.92 27.56,80.92 27.27,81.22 27.27,82.26 27.13,82.4 26.94,82.4 26.81,82.26 26.81,81.22 26.51,80.92 26.09,80.92 25.79,81.22 25.79,82.26 25.66,82.4 25.47,82.4 25.33,82.26 25.33,81.22 25.04,80.92 24.62,80.92 24.32,81.22 24.32,82.26 24.19,82.4 24,82.4 23.86,82.26 23.86,81.22 23.56,80.92 23.14,80.92 22.85,81.22 22.85,82.26 22.71,82.4 22.52,82.4 22.39,82.26 22.39,81.22 22.09,80.92 21.67,80.92 21.37,81.22 21.37,82.26 21.24,82.4 21.05,82.4 20.92,82.26 20.92,81.22 20.62,80.92 20.2,80.92 19.9,81.22 19.9,82.26 19.77,82.4 19.58,82.4 19.44,82.26 19.44,81.22 19.14,80.92 18.72,80.92 18.43,81.22 18.43,81.53 18.29,81.66 17.51,81.66 16.37,82.8 15.21,82.8 11.76,79.35 10.06,79.35 9.25,78.54 v2(9.22,78.54)
  BOTTOM w0.152: J13.81 7.71,78.54 7.78,78.61 8.51,78.61 8.56,78.56 9.2,78.56 v2(9.22,78.54)
DA13P: length 67.2
  TOP w0.127: U1.A5 43.22,72.75 43.22,73.16
  TOP w0.152: v2(8.76,79.04) 8.81,78.99 9.31,78.99 9.94,79.63 11.64,79.63 15.09,83.08 16.48,83.08 17.63,81.94 18.41,81.94 18.71,81.64 18.71,81.34 18.84,81.2 19.03,81.2 19.16,81.34 19.16,82.38 19.46,82.68 19.88,82.68 20.18,82.38 20.18,81.34 20.31,81.2 20.5,81.2 20.64,81.34 20.64,82.38 20.93,82.68 21.35,82.68 21.65,82.38 21.65,81.34 21.79,81.2 21.98,81.2 22.11,81.34 22.11,82.38 22.41,82.68 22.83,82.68 23.13,82.38 23.13,81.34 23.26,81.2 23.45,81.2 23.58,81.34 23.58,82.38 23.88,82.68 24.3,82.68 24.6,82.38 24.6,81.34 24.73,81.2 24.92,81.2 25.06,81.34 25.06,82.38 25.35,82.68 25.77,82.68 26.07,82.38 26.07,81.34 26.21,81.2 26.39,81.2 26.53,81.34 26.53,82.38 26.83,82.68 27.25,82.68 27.54,82.38 27.54,81.34 27.68,81.2 27.87,81.2 28,81.34 28,82.38 28.3,82.68 28.72,82.68 29.02,82.38 29.02,81.34 29.15,81.2 29.34,81.2 29.48,81.34 29.48,82.38 29.77,82.68 30.19,82.68 30.49,82.38 30.49,81.34 30.63,81.2 30.81,81.2 30.95,81.34 30.95,82.38 31.25,82.68 31.67,82.68 31.96,82.38 31.96,81.34 32.1,81.2 32.29,81.2 32.42,81.34 32.42,82.38 32.72,82.68 33.14,82.68 33.44,82.38 33.44,82.07 33.57,81.94 36.31,81.94 43.22,75.03 43.22,73.16
  BOTTOM w0.152: J13.79 7.71,79.04 7.78,78.97 8.69,78.97 v2(8.76,79.04)
DA14N: length 67.7
  TOP w0.127: 43.73,73.06 43.73,72.27 44.14,71.86 U1.B6
  TOP w0.152: v2(9.19,80.04) 9.58,80.42 11.23,80.42 15.32,84.51 16.48,84.51 16.61,84.37 16.61,84.19 16.91,83.9 17.33,83.9 17.63,84.19 17.63,84.98 17.76,85.12 17.95,85.12 18.08,84.98 18.08,84.19 18.38,83.9 18.8,83.9 19.1,84.19 19.1,84.98 19.23,85.12 19.42,85.12 19.56,84.98 19.56,84.19 19.85,83.9 20.27,83.9 20.57,84.19 20.57,84.98 20.71,85.12 20.89,85.12 21.03,84.98 21.03,84.19 21.33,83.9 21.75,83.9 22.04,84.19 22.04,84.98 22.18,85.12 22.37,85.12 22.5,84.98 22.5,84.19 22.8,83.9 23.22,83.9 23.52,84.19 23.52,84.98 23.65,85.12 23.84,85.12 23.98,84.98 23.98,84.19 24.27,83.9 24.69,83.9 24.99,84.19 24.99,84.98 25.12,85.12 25.31,85.12 25.45,84.98 25.45,84.19 25.75,83.9 26.17,83.9 26.46,84.19 26.46,84.98 26.6,85.12 26.79,85.12 26.92,84.98 26.92,84.19 27.22,83.9 27.64,83.9 27.94,84.19 27.94,84.98 28.07,85.12 28.26,85.12 28.39,84.98 28.39,84.19 28.69,83.9 29.11,83.9 29.41,84.19 29.41,84.98 29.54,85.12 29.73,85.12 29.87,84.98 29.87,84.19 30.17,83.9 30.59,83.9 30.88,84.19 30.88,84.98 31.02,85.12 31.21,85.12 31.34,84.98 31.34,84.19 31.64,83.9 32.06,83.9 32.36,84.19 32.36,84.98 32.49,85.12 32.68,85.12 32.81,84.98 32.81,84.19 33.11,83.9 33.53,83.9 33.83,84.19 33.83,84.37 33.96,84.51 35.1,84.51 43.73,75.88 43.73,73.06
  BOTTOM w0.152: J13.75 7.71,80.04 7.8,80.14 8.49,80.14 8.56,80.06 9.17,80.06 v2(9.19,80.04)
DA14P: length 67.2
  TOP w0.152: v2(8.76,80.54) 9.3,80.54 9.45,80.7 11.11,80.7 15.2,84.79 16.59,84.79 16.89,84.49 16.89,84.31 17.02,84.18 17.21,84.18 17.35,84.31 17.35,85.1 17.64,85.39 18.06,85.39 18.36,85.1 18.36,84.31 18.5,84.18 18.69,84.18 18.82,84.31 18.82,85.1 19.12,85.39 19.54,85.39 19.83,85.1 19.83,84.31 19.97,84.18 20.16,84.18 20.29,84.31 20.29,85.1 20.59,85.39 21.01,85.39 21.31,85.1 21.31,84.31 21.44,84.18 21.63,84.18 21.77,84.31 21.77,85.1 22.06,85.39 22.48,85.39 22.78,85.1 22.78,84.31 22.92,84.18 23.1,84.18 23.24,84.31 23.24,85.1 23.54,85.39 23.96,85.39 24.25,85.1 24.25,84.31 24.39,84.18 24.58,84.18 24.71,84.31 24.71,85.1 25.01,85.39 25.43,85.39 25.73,85.1 25.73,84.31 25.86,84.18 26.05,84.18 26.18,84.31 26.18,85.1 26.48,85.39 26.9,85.39 27.2,85.1 27.2,84.31 27.33,84.18 27.52,84.18 27.66,84.31 27.66,85.1 27.96,85.39 28.38,85.39 28.67,85.1 28.67,84.31 28.81,84.18 29,84.18 29.13,84.31 29.13,85.1 29.43,85.39 29.85,85.39 30.15,85.1 30.15,84.31 30.28,84.18 30.47,84.18 30.6,84.31 30.6,85.1 30.9,85.39 31.32,85.39 31.62,85.1 31.62,84.31 31.75,84.18 31.94,84.18 32.08,84.31 32.08,85.1 32.38,85.39 32.8,85.39 33.09,85.1 33.09,84.31 33.23,84.18 33.42,84.18 33.55,84.31 33.55,84.49 33.85,84.79 35.22,84.79 44.01,75.99 44.01,72.76 U1.A6
  BOTTOM w0.152: J13.73 7.71,80.54 7.79,80.47 8.69,80.47 v2(8.76,80.54)
DA15N: length 67.8
  TOP w0.127: 44.55,72.83 44.55,72.47 44.94,72.08 U1.B7
  TOP w0.152: 44.55,72.83 44.55,76.54 34.52,86.56 33.03,86.56 32.62,86.16 32.2,86.16 31.9,86.45 31.9,87.19 31.77,87.33 31.58,87.33 31.44,87.19 31.44,86.45 31.15,86.16 30.72,86.16 30.43,86.45 30.43,87.19 30.29,87.33 30.1,87.33 29.97,87.19 29.97,86.45 29.67,86.16 29.25,86.16 28.95,86.45 28.95,87.19 28.82,87.33 28.63,87.33 28.5,87.19 28.5,86.45 28.2,86.16 27.78,86.16 27.48,86.45 27.48,87.19 27.35,87.33 27.16,87.33 27.02,87.19 27.02,86.45 26.73,86.16 26.31,86.16 26.01,86.45 26.01,87.19 25.87,87.33 25.68,87.33 25.55,87.19 25.55,86.45 25.25,86.16 24.83,86.16 24.53,86.45 24.53,87.19 24.4,87.33 24.21,87.33 24.08,87.19 24.08,86.45 23.78,86.16 23.36,86.16 23.06,86.45 23.06,87.19 22.93,87.33 22.74,87.33 22.6,87.19 22.6,86.45 22.31,86.16 21.89,86.16 21.59,86.45 21.59,87.19 21.45,87.33 21.26,87.33 21.13,87.19 21.13,86.45 20.83,86.16 20.41,86.16 20.12,86.45 20.12,87.19 19.98,87.33 19.79,87.33 19.66,87.19 19.66,86.45 19.36,86.16 18.94,86.16 18.64,86.45 18.64,87.19 18.51,87.33 18.32,87.33 18.18,87.19 18.18,86.45 17.89,86.16 17.47,86.16 17.17,86.45 17.17,87.19 17.03,87.33 16.85,87.33 16.71,87.19 16.71,87.04 16.41,86.74 15.24,86.74 10.49,81.99 9.55,81.99 9.17,81.61 v2(9.17,81.53)
  BOTTOM w0.152: J13.69 7.71,81.54 8.55,81.54 8.56,81.53 v2(9.17,81.53)
DA15P: length 67.3
  TOP w0.127: 44.86,72.76 44.86,72.79 44.82,72.83
  TOP w0.152: 44.82,72.83 44.82,76.65 34.63,86.84 32.91,86.84 32.5,86.44 32.31,86.44 32.18,86.57 32.18,87.31 31.88,87.6 31.46,87.6 31.16,87.31 31.16,86.57 31.03,86.44 30.84,86.44 30.71,86.57 30.71,87.31 30.41,87.6 29.99,87.6 29.69,87.31 29.69,86.57 29.56,86.44 29.37,86.44 29.23,86.57 29.23,87.31 28.94,87.6 28.52,87.6 28.22,87.31 28.22,86.57 28.08,86.44 27.89,86.44 27.76,86.57 27.76,87.31 27.46,87.6 27.04,87.6 26.74,87.31 26.74,86.57 26.61,86.44 26.42,86.44 26.29,86.57 26.29,87.31 25.99,87.6 25.57,87.6 25.27,87.31 25.27,86.57 25.14,86.44 24.95,86.44 24.81,86.57 24.81,87.31 24.52,87.6 24.1,87.6 23.8,87.31 23.8,86.57 23.66,86.44 23.47,86.44 23.34,86.57 23.34,87.31 23.04,87.6 22.62,87.6 22.32,87.31 22.32,86.57 22.19,86.44 22,86.44 21.87,86.57 21.87,87.31 21.57,87.6 21.15,87.6 20.85,87.31 20.85,86.57 20.72,86.44 20.53,86.44 20.39,86.57 20.39,87.31 20.1,87.6 19.68,87.6 19.38,87.31 19.38,86.57 19.24,86.44 19.06,86.44 18.92,86.57 18.92,87.31 18.62,87.6 18.2,87.6 17.91,87.31 17.91,86.57 17.77,86.44 17.58,86.44 17.45,86.57 17.45,87.31 17.15,87.6 16.73,87.6 16.43,87.31 16.43,87.15 16.3,87.02 15.12,87.02 10.37,82.27 9.43,82.27 9.21,82.04 v2(8.74,82.04) ; U1.A7 44.86,72.72 44.86,72.76
  BOTTOM w0.152: v2(8.74,82.04) 8.66,81.97 7.79,81.97 7.71,82.04 J13.67
DAC_DACCLK: length 4.5
  TOP w0.102: 48.94,73.08 U1.A12
  TOP w0.152: 48.94,73.08 48.94,73.42 49.4,73.89 49.83,73.89 50.29,74.35 50.29,74.65 50.7,75.06 R15.2 50.8,76.07
DAC_DACCLKC: length 4.5
  TOP w0.102: 48.59,73.08 48.58,73.08 U1.A11
  TOP w0.152: 49.78,76.07 R15.1 49.99,74.85 49.99,74.47 49.71,74.19 49.28,74.19 48.63,73.55 48.63,73.45 48.63,73.12 48.59,73.08
DAC_FIFO_OSTR: length 4.5
  TOP w0.102: 46.79,72.95 46.79,72.82 46.6,72.64 U1.A9
  TOP w0.127: R5.2 46.39,74.71 46.19,74.71 46.01,74.54 46.01,73.34 46.25,73.1 46.63,73.1 46.79,72.95
  TOP w0.152: R5.2 46.74,76.07
DAC_FIFO_OSTRC: length 4.6
  TOP w0.127: U1.B9 46.13,72.24 46.13,72.8 45.72,73.21
  TOP w0.152: 45.72,76.07 R5.1 45.72,73.21
DAC_RESET: length 99.8
  TOP w0.152: 89.45,125.3 SW1.4 ; 89.45,125.3 89.45,126.31 ; 89.45,125.3 v2(89.46,125.3) ; 89.45,126.31 v2(89.46,126.31) ; 89.45,126.31 SW1.3
  BOTTOM w0.102: U1.N10 47.34,63.02 47.74,62.62 51,62.62
  BOTTOM w0.152: v2(89.46,125.3) 92.58,122.17 92.58,117.07 95.17,114.48 95.17,105.03 93.24,103.1 86.54,103.1 77.55,94.11 76.99,94.11 76.3,93.42 76.3,92.79 72.67,89.15 71.53,89.15 69.72,87.35 69.72,87.33 54.74,72.34 54.74,64.72 53.11,63.09 51.48,63.09 51,62.62
  BOTTOM w0.254: R46.1 v2(89.46,126.31) ; C47.1 v2(89.46,125.3)
DACCLK: length 39.1
  TOP w0.152: U2.20 63.6,109.3 63.6,106.48 64.77,105.31 64.77,104.4 65.1,104.06 R62.2 ; R155.1 50.47,79.45 50.47,80.06 52.81,82.4 52.81,90.27 53.82,91.29 57.17,91.29 64.74,98.86 64.74,102.64 R66.1
  TOP w0.305: R62.2 R66.1
DACCLKC: length 39.1
  TOP w0.152: R154.1 50.17,79.5 50.17,80.19 52.5,82.52 52.5,90.4 53.7,91.59 57.05,91.59 64.44,98.98 64.44,102.65 R67.1 ; R63.2 64.47,104.39 64.47,105.18 63.3,106.35 63.3,109.32 U2.19
  TOP w0.305: R63.2 R67.1
DATACLK-N: length 18.6
  TOP w0.152: v2(8.84,69.29) 8.85,69.29 9.51,68.63 10.95,68.63 12.19,69.88 13.17,69.88 13.49,69.55 13.49,69.36 13.36,69.23 12.58,69.23 12.28,68.93 12.28,68.51 12.58,68.21 13.36,68.21 13.49,68.08 13.49,67.89 13.36,67.75 12.58,67.75 12.28,67.46 12.28,67.04 12.58,66.74 14.16,66.74 15.63,68.21 16.36,68.21 16.37,68.2 17.93,68.2 SJP10.2
  BOTTOM w0.152: J13.117 7.71,69.54 7.75,69.49 8.64,69.49 v2(8.84,69.29)
DATACLK-P: length 18.2
  TOP w0.152: v2(9.14,69.98) 9.14,69.63 9.3,69.48 9.3,69.24 9.63,68.91 9.8,68.91 10.01,69.11 10.24,69.11 10.44,68.91 10.83,68.91 12.08,70.15 13.28,70.15 13.77,69.67 13.77,69.25 13.47,68.95 12.7,68.95 12.56,68.81 12.56,68.62 12.7,68.49 13.47,68.49 13.77,68.19 13.77,67.77 13.47,67.48 12.7,67.48 12.56,67.34 12.56,67.15 12.7,67.02 14.04,67.02 15.52,68.49 16.48,68.49 16.49,68.48 16.54,68.48 SJP9.2
  BOTTOM w0.152: J13.115 7.71,70.04 7.83,70.04 7.89,70.1 8.31,70.1 8.59,69.82 8.99,69.82 v2(9.14,69.98)
DATACLKN: length 10.4
  L6_PWR w0.127: v2(32.49,68.12) 32.17,67.79 31.83,67.79 31.62,68 31.62,68.33 31.9,68.61 32.84,68.61 33.47,67.97 40.01,67.97 U1.G1
DATACLKP: length 10.1
  L6_PWR w0.127: U1.G2 40.7,67.84 40.3,68.23 39.98,68.23 39.97,68.22 33.58,68.22 32.94,68.86 31.78,68.86 31.6,68.68 v2(31.29,68.68)
DB0N: length 67.1
  BOTTOM w0.127: U1.P7 44.8,62.1 44.8,61.71 44.81,61.69 44.81,61.68
  BOTTOM w0.152: 44.81,61.68 44.81,58.71 41.64,55.54 41.64,52.54 36.37,47.27 35.35,47.27 35.05,47.57 35.05,47.77 34.92,47.9 34.73,47.9 34.6,47.77 34.6,46.93 34.3,46.63 33.88,46.63 33.58,46.93 33.58,47.77 33.45,47.9 33.26,47.9 33.12,47.77 33.12,46.93 32.83,46.63 32.4,46.63 32.11,46.93 32.11,47.77 31.97,47.9 31.78,47.9 31.65,47.77 31.65,46.93 31.35,46.63 30.93,46.63 30.63,46.93 30.63,47.77 30.5,47.9 30.31,47.9 30.18,47.77 30.18,46.93 29.88,46.63 29.46,46.63 29.16,46.93 29.16,47.77 29.03,47.9 28.84,47.9 28.7,47.77 28.7,46.93 28.41,46.63 27.98,46.63 27.69,46.93 27.69,47.77 27.55,47.9 27.36,47.9 27.23,47.77 27.23,46.93 26.93,46.63 26.51,46.63 26.21,46.93 26.21,47.77 26.08,47.9 25.89,47.9 25.76,47.77 25.76,46.93 25.46,46.63 25.04,46.63 24.74,46.93 24.74,47.77 24.61,47.9 24.42,47.9 24.28,47.77 24.28,46.93 23.99,46.63 23.57,46.63 23.27,46.93 23.27,47.77 23.13,47.9 22.94,47.9 22.81,47.77 22.81,46.93 22.51,46.63 22.09,46.63 21.79,46.93 21.79,47.77 21.66,47.9 21.47,47.9 21.34,47.77 21.34,46.93 21.04,46.63 20.62,46.63 20.32,46.93 20.32,47.77 20.19,47.9 20,47.9 19.86,47.77 19.86,46.93 19.57,46.63 19.15,46.63 18.85,46.93 18.85,47.14 18.71,47.27 17.55,47.27 16.93,47.89 16.93,50.82 15.6,52.16 15.6,52.17 15.25,52.51 v2(14.92,52.51) 14.83,52.6 13.97,52.6 13.88,52.51 J13.166
DB0P: length 67.8
  BOTTOM w0.127: U1.N7 44.53,62.63 44.53,61.68
  BOTTOM w0.152: J13.164 13.88,53.01 13.96,52.93 14.66,52.93 14.72,53 15.35,53 v2(15.37,53.01) 15.4,52.98 15.4,52.77 15.88,52.28 15.88,52.27 17.21,50.94 17.21,48.01 17.67,47.55 18.83,47.55 19.13,47.25 19.13,47.05 19.26,46.91 19.45,46.91 19.58,47.05 19.58,47.89 19.88,48.18 20.3,48.18 20.6,47.89 20.6,47.05 20.73,46.91 20.92,46.91 21.06,47.05 21.06,47.89 21.36,48.18 21.78,48.18 22.07,47.89 22.07,47.05 22.21,46.91 22.4,46.91 22.53,47.05 22.53,47.89 22.83,48.18 23.25,48.18 23.55,47.89 23.55,47.05 23.68,46.91 23.87,46.91 24,47.05 24,47.89 24.3,48.18 24.72,48.18 25.02,47.89 25.02,47.05 25.15,46.91 25.34,46.91 25.48,47.05 25.48,47.89 25.78,48.18 26.2,48.18 26.49,47.89 26.49,47.05 26.63,46.91 26.82,46.91 26.95,47.05 26.95,47.89 27.25,48.18 27.67,48.18 27.97,47.89 27.97,47.05 28.1,46.91 28.29,46.91 28.42,47.05 28.42,47.89 28.72,48.18 29.14,48.18 29.44,47.89 29.44,47.05 29.57,46.91 29.76,46.91 29.9,47.05 29.9,47.89 30.19,48.18 30.62,48.18 30.91,47.89 30.91,47.05 31.05,46.91 31.24,46.91 31.37,47.05 31.37,47.89 31.67,48.18 32.09,48.18 32.39,47.89 32.39,47.05 32.52,46.91 32.71,46.91 32.84,47.05 32.84,47.89 33.14,48.18 33.56,48.18 33.86,47.89 33.86,47.05 33.99,46.91 34.18,46.91 34.32,47.05 34.32,47.89 34.61,48.18 35.04,48.18 35.33,47.89 35.33,47.68 35.47,47.55 36.26,47.55 41.36,52.65 41.36,55.65 44.53,58.82 44.53,61.68
DB1N: length 67.2
  BOTTOM w0.127: U1.P6 44.07,62.17 44.07,61.79
  BOTTOM w0.152: J13.160 13.88,54.02 13.97,54.1 14.86,54.1 v2(14.95,54.02) 15.82,54.02 16.28,53.55 16.28,52.75 17.8,51.24 17.8,50.28 18.39,49.69 18.39,49.67 19.24,48.82 19.66,48.82 19.96,49.12 19.96,50.06 20.1,50.19 20.29,50.19 20.42,50.06 20.42,49.12 20.72,48.82 21.14,48.82 21.44,49.12 21.44,50.06 21.57,50.19 21.76,50.19 21.89,50.06 21.89,49.12 22.19,48.82 22.61,48.82 22.91,49.12 22.91,50.06 23.04,50.19 23.23,50.19 23.37,50.06 23.37,49.12 23.66,48.82 24.08,48.82 24.38,49.12 24.38,50.06 24.52,50.19 24.71,50.19 24.84,50.06 24.84,49.12 25.14,48.82 25.56,48.82 25.85,49.12 25.85,50.06 25.99,50.19 26.18,50.19 26.31,50.06 26.31,49.12 26.61,48.82 27.03,48.82 27.33,49.12 27.33,50.06 27.46,50.19 27.65,50.19 27.79,50.06 27.79,49.12 28.08,48.82 28.5,48.82 28.8,49.12 28.8,50.06 28.94,50.19 29.12,50.19 29.26,50.06 29.26,49.12 29.56,48.82 29.98,48.82 30.27,49.12 30.27,50.06 30.41,50.19 30.6,50.19 30.73,50.06 30.73,49.12 31.03,48.82 31.45,48.82 31.75,49.12 31.75,50.06 31.88,50.19 32.07,50.19 32.2,50.06 32.2,49.12 32.5,48.82 32.92,48.82 33.22,49.12 33.22,50.06 33.35,50.19 33.54,50.19 33.68,50.06 33.68,49.12 33.98,48.82 34.4,48.82 34.69,49.12 34.69,50.06 34.83,50.19 35.02,50.19 35.15,50.06 35.15,49.12 35.45,48.82 35.87,48.82 36.56,49.5 37.34,49.5 40.79,52.96 40.79,55.73 44.07,59 44.07,61.79
DB1P: length 67.8
  BOTTOM w0.127: 43.75,61.72 43.75,62.64 U1.N6
  BOTTOM w0.152: J13.158 13.88,54.52 13.96,54.43 14.68,54.43 14.75,54.5 15.38,54.5 v2(15.39,54.51) 15.61,54.3 15.94,54.3 16.56,53.67 16.56,52.87 18.08,51.35 18.08,50.4 18.67,49.8 18.67,49.78 19.36,49.1 19.55,49.1 19.68,49.23 19.68,50.17 19.98,50.47 20.4,50.47 20.7,50.17 20.7,49.23 20.83,49.1 21.02,49.1 21.16,49.23 21.16,50.17 21.45,50.47 21.87,50.47 22.17,50.17 22.17,49.23 22.31,49.1 22.5,49.1 22.63,49.23 22.63,50.17 22.93,50.47 23.35,50.47 23.65,50.17 23.65,49.23 23.78,49.1 23.97,49.1 24.1,49.23 24.1,50.17 24.4,50.47 24.82,50.47 25.12,50.17 25.12,49.23 25.25,49.1 25.44,49.1 25.58,49.23 25.58,50.17 25.87,50.47 26.29,50.47 26.59,50.17 26.59,49.23 26.73,49.1 26.91,49.1 27.05,49.23 27.05,50.17 27.35,50.47 27.77,50.47 28.06,50.17 28.06,49.23 28.2,49.1 28.39,49.1 28.52,49.23 28.52,50.17 28.82,50.47 29.24,50.47 29.54,50.17 29.54,49.23 29.67,49.1 29.86,49.1 30,49.23 30,50.17 30.29,50.47 30.71,50.47 31.01,50.17 31.01,49.23 31.14,49.1 31.33,49.1 31.47,49.23 31.47,50.17 31.77,50.47 32.19,50.47 32.48,50.17 32.48,49.23 32.62,49.1 32.81,49.1 32.94,49.23 32.94,50.17 33.24,50.47 33.66,50.47 33.96,50.17 33.96,49.23 34.09,49.1 34.28,49.1 34.41,49.23 34.41,50.17 34.71,50.47 35.13,50.47 35.43,50.17 35.43,49.23 35.56,49.1 35.75,49.1 36.44,49.78 37.22,49.78 40.51,53.07 40.51,55.84 43.79,59.12 43.79,61.67 43.75,61.72
DB2N: length 67.2
  BOTTOM w0.127: U1.P5 43.23,62.13 43.23,60.05
  BOTTOM w0.152: 43.23,60.05 43.22,60.03 43.22,59.09 39.88,55.75 39.88,53.38 38.22,51.71 37.26,51.71 36.96,52.01 36.96,52.32 36.83,52.45 36.64,52.45 36.5,52.32 36.5,51.28 36.21,50.98 35.78,50.98 35.49,51.28 35.49,52.32 35.35,52.45 35.16,52.45 35.03,52.32 35.03,51.28 34.73,50.98 34.31,50.98 34.01,51.28 34.01,52.32 33.88,52.45 33.69,52.45 33.56,52.32 33.56,51.28 33.26,50.98 32.84,50.98 32.54,51.28 32.54,52.32 32.41,52.45 32.22,52.45 32.08,52.32 32.08,51.28 31.79,50.98 31.37,50.98 31.07,51.28 31.07,52.32 30.93,52.45 30.74,52.45 30.61,52.32 30.61,51.28 30.31,50.98 29.89,50.98 29.59,51.28 29.59,52.32 29.46,52.45 29.27,52.45 29.14,52.32 29.14,51.28 28.84,50.98 28.42,50.98 28.12,51.28 28.12,52.32 27.99,52.45 27.8,52.45 27.66,52.32 27.66,51.28 27.37,50.98 26.95,50.98 26.65,51.28 26.65,52.32 26.51,52.45 26.32,52.45 26.19,52.32 26.19,51.28 25.89,50.98 25.47,50.98 25.17,51.28 25.17,52.32 25.04,52.45 24.85,52.45 24.72,52.32 24.72,51.28 24.42,50.98 24,50.98 23.7,51.28 23.7,52.32 23.57,52.45 23.38,52.45 23.24,52.32 23.24,51.28 22.95,50.98 22.53,50.98 22.23,51.28 22.23,52.32 22.09,52.45 21.91,52.45 21.77,52.32 21.77,51.28 21.47,50.98 21.05,50.98 20.76,51.28 20.76,52.32 20.62,52.45 20.43,52.45 20.3,52.32 20.3,52.01 20,51.71 18.71,51.71 17.04,53.38 17.04,54.49 15.89,55.65 15.74,55.65 15.62,55.52 15.54,55.52 15.54,55.52 v2(14.95,55.52) 14.87,55.6 13.96,55.6 13.88,55.52 J13.154
DB2P: length 67.7
  BOTTOM w0.127: U1.N5 43.31,63.04 42.93,62.66 42.93,62.05 42.95,62.03 42.95,60.16
  BOTTOM w0.152: J13.152 13.88,56.02 13.97,55.93 14.68,55.93 14.75,56 15.41,56 v2(15.42,56.01) 15.49,55.93 16,55.93 17.32,54.61 17.32,53.49 18.82,51.99 19.88,51.99 20.02,52.13 20.02,52.43 20.32,52.73 20.74,52.73 21.03,52.43 21.03,51.39 21.17,51.26 21.36,51.26 21.49,51.39 21.49,52.43 21.79,52.73 22.21,52.73 22.51,52.43 22.51,51.39 22.64,51.26 22.83,51.26 22.97,51.39 22.97,52.43 23.26,52.73 23.68,52.73 23.98,52.43 23.98,51.39 24.12,51.26 24.3,51.26 24.44,51.39 24.44,52.43 24.74,52.73 25.16,52.73 25.45,52.43 25.45,51.39 25.59,51.26 25.78,51.26 25.91,51.39 25.91,52.43 26.21,52.73 26.63,52.73 26.93,52.43 26.93,51.39 27.06,51.26 27.25,51.26 27.38,51.39 27.38,52.43 27.68,52.73 28.1,52.73 28.4,52.43 28.4,51.39 28.53,51.26 28.72,51.26 28.86,51.39 28.86,52.43 29.16,52.73 29.58,52.73 29.87,52.43 29.87,51.39 30.01,51.26 30.2,51.26 30.33,51.39 30.33,52.43 30.63,52.73 31.05,52.73 31.35,52.43 31.35,51.39 31.48,51.26 31.67,51.26 31.8,51.39 31.8,52.43 32.1,52.73 32.52,52.73 32.82,52.43 32.82,51.39 32.95,51.26 33.14,51.26 33.28,51.39 33.28,52.43 33.57,52.73 34,52.73 34.29,52.43 34.29,51.39 34.43,51.26 34.62,51.26 34.75,51.39 34.75,52.43 35.05,52.73 35.47,52.73 35.77,52.43 35.77,51.39 35.9,51.26 36.09,51.26 36.22,51.39 36.22,52.43 36.52,52.73 36.94,52.73 37.24,52.43 37.24,52.13 37.37,51.99 38.1,51.99 39.6,53.49 39.6,55.87 42.94,59.21 42.94,60.15 42.95,60.16
